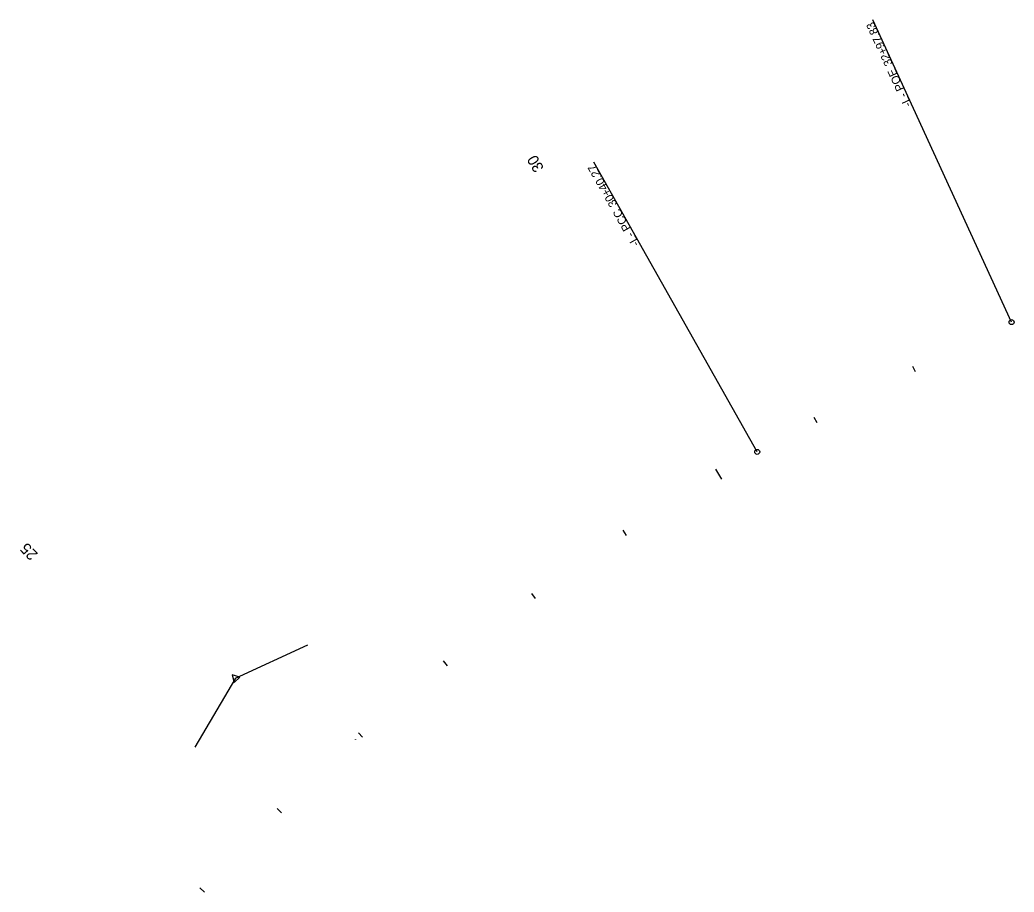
# Model space of a CAD drawing. Extents: x 2379555 to 2381342, y 331421 to 333377.
# Drawn here: x 2380446 to 2381342, y 332590 to 333377 of the extents above; entities that cross this region are included whole.
import ezdxf

# ---------------------------------------------------------------- set-up
doc = ezdxf.new("R2010")
doc.units = 0
for name, color, linetype in [('_CIVIL_CONSTRUCTION', 7, 'Continuous'), ('Default', 7, 'Continuous'), ('P_NCDOT_Horizontal_Alignment_Station_Label', 7, 'Continuous'), ('P_NCDOT_Horizontal_Alignment_Station_Major_Label', 7, 'Continuous'), ('P_NCDOT_Horizontal_Alignment_Tick_Large', 7, 'Continuous'), ('P_NCDOT_Horizontal_Alignment_Tick_Small', 7, 'Continuous')]:
    doc.layers.add(name, color=color, linetype=linetype)

msp = doc.modelspace()

# ---------------------------------------------------------------- linework, layer by layer
at = {"layer": '_CIVIL_CONSTRUCTION'}
msp.add_circle((2380748.17, 332727.9), 0.05, dxfattribs=at)
at = {"layer": 'Default'}
for q in [(2380705.26, 332813.07), (2380603.4, 332720.93), (2380639.83, 332783.03)]:
    msp.add_line((2380639.83, 332783.03), q, dxfattribs=at)
msp.add_lwpolyline([(2380637, 332786.07), (2380638.61, 332779.06), (2380643.88, 332783.96)], close=True, dxfattribs=at)
at = {"layer": 'P_NCDOT_Horizontal_Alignment_Station_Label'}
for p, q in [((2381339.62, 333104.3), (2381214.45, 333376.94)), ((2381110.28, 332987.25), (2380962.91, 333248.56))]:
    msp.add_line(p, q, dxfattribs=at)
for centre in [(2381339.62, 333104.3), (2381110.28, 332987.25)]:
    msp.add_circle(centre, 2.25, dxfattribs=at)
at = {"layer": 'P_NCDOT_Horizontal_Alignment_Tick_Large'}
msp.add_line((2381072.68, 332971.72), (2381078.08, 332962.58), dxfattribs=at)
at = {"layer": 'P_NCDOT_Horizontal_Alignment_Tick_Small'}
for p, q in [((2381250.14, 333064.56), (2381252.6, 333059.62)), ((2381161.28, 333018.51), (2381163.89, 333013.65)), ((2380989.01, 332916.56), (2380992.05, 332911.94)), ((2380906.7, 332859.56), (2380909.95, 332855.1)), ((2380827.24, 332798.64), (2380830.7, 332794.35)), ((2380750.82, 332733.95), (2380754.48, 332729.83)), ((2380677.62, 332665.64), (2380681.48, 332661.7)), ((2380607.81, 332593.86), (2380611.86, 332590.11))]:
    msp.add_line(p, q, dxfattribs=at)

# ---------------------------------------------------------------- texts
at = {"layer": 'P_NCDOT_Horizontal_Alignment_Station_Label'}
for s, rotation, p in [('32+97.83', 114.65961, (2381232.6, 333337.41)), ('POE', 114.65961, (2381243.05, 333314.65)), ('L', 114.65961, (2381248.15, 333303.54)), ('- ', 114.65961, (2381245.72, 333308.83)), ('-', 114.65961, (2381249.6, 333300.37)), ('30+40.27', 119.41993, (2380984.28, 333210.67)), ('PCC', 119.41993, (2380996.58, 333188.86)), ('L', 119.41993, (2381002.59, 333178.21)), ('- ', 119.41993, (2380999.72, 333183.28)), ('-', 119.41993, (2381004.3, 333175.17))]:
    msp.add_text(s, height=7.5, rotation=rotation, dxfattribs=at).set_placement(p)
at = {"layer": 'P_NCDOT_Horizontal_Alignment_Station_Major_Label'}
for s, rotation, p in [('30', 120.5372, (2380918.34, 333243.2)), ('25', 134.05771, (2380462.34, 332895.34))]:
    msp.add_text(s, height=10, rotation=rotation, dxfattribs=at).set_placement(p)

doc.saveas('drawing.dxf')
